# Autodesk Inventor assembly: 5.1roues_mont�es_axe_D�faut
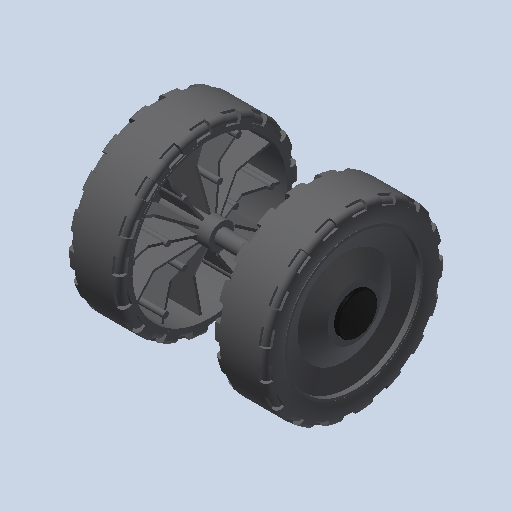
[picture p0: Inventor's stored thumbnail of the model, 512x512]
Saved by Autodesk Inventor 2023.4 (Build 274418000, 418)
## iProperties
Created: 2011-01
Part Number: 5.1roues_mont�es_axe_D�faut
Document SubType Name: Assembly
Designer: eric
Mass: 610.809 g
Surface Area: 3296.9 cm^2
Volume: 610.809 cm^3
Density: 1 g/cm^3
Author: eric
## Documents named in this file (5)
- C:\Users\bruno\Documents\1-Cours-2024-25\TSsI\7-Dynamique\chariot de golf\chariot_de_golf\chariot_de_golf_trolem\5.1roues_montees_axe_Defaut.iam
- C:\Users\bruno\Documents\1-Cours-2024-25\TSsI\7-Dynamique\chariot de golf\chariot_de_golf\chariot_de_golf_trolem\5.1Anneaugrifaxe12_Defaut.ipt
- C:\Users\bruno\Documents\1-Cours-2024-25\TSsI\7-Dynamique\chariot de golf\chariot_de_golf\chariot_de_golf_trolem\9envoliveur_Defaut.ipt
- C:\Users\bruno\Documents\1-Cours-2024-25\TSsI\7-Dynamique\chariot de golf\chariot_de_golf\chariot_de_golf_trolem\5.1roue_avant_montee_Defaut.iam
- C:\Users\bruno\Documents\1-Cours-2024-25\TSsI\7-Dynamique\chariot de golf\chariot_de_golf\chariot_de_golf_trolem\5.1axe e12_Defaut.ipt
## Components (7 placed, 4 different names)
1. 9envoliveur_Defaut:1
2. 5.1roue_avant_montee_Defaut:1 [sub-assembly]
3. 5.1Anneaugrifaxe12_Defaut:3
4. 9envoliveur_Defaut:2
5. 5.1axe e12_Defaut:1
6. 5.1roue_avant_montee_Defaut:2 [sub-assembly]
7. 5.1Anneaugrifaxe12_Defaut:2
